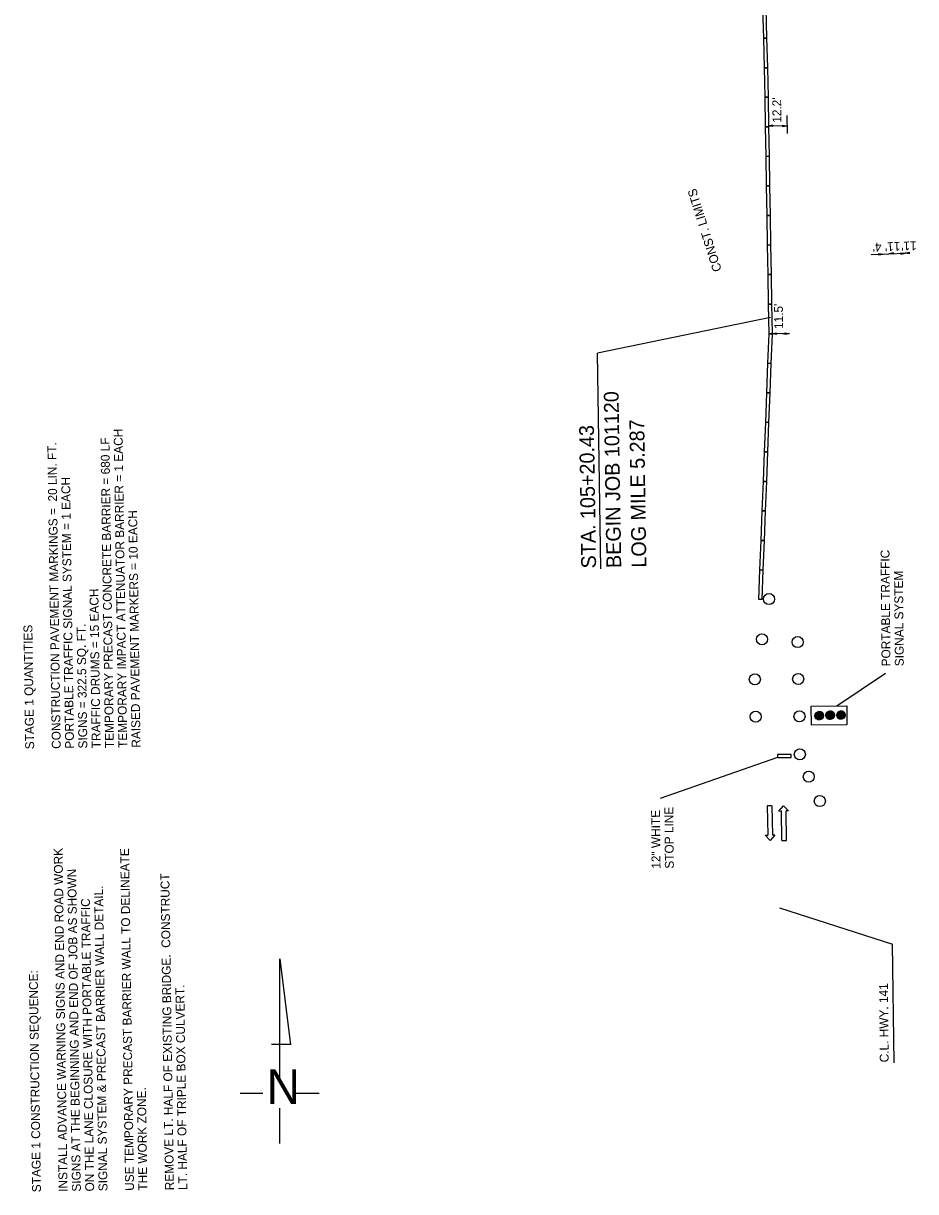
# Model space of a CAD drawing. Extents: x 1770018 to 1773492, y 718230 to 729141.
# Drawn here: x 1770318 to 1770922, y 724066 to 724857 of the extents above; entities that cross this region are included whole.
import ezdxf

# ---------------------------------------------------------------- set-up
doc = ezdxf.new("R2010")
doc.units = 0
for name, color, linetype in [('Default', 7, 'Continuous'), ('R_Border Notes', 7, 'Continuous'), ('R_Dimension', 7, 'Continuous'), ('R_Draft', 7, 'Continuous'), ('R_Horz Alg Annot', 7, 'Continuous'), ('R_MOT', 7, 'Continuous'), ('R_Proposed Road', 7, 'Continuous'), ('R_Striping', 7, 'Continuous'), ('T_Vehicle Path Rt', 7, 'Continuous')]:
    doc.layers.add(name, color=color, linetype=linetype)

msp = doc.modelspace()

# ---------------------------------------------------------------- linework, layer by layer
at = {"layer": 'Default'}
for p, q in [((1770823.66, 724657.68), (1770706.62, 724633.36)), ((1770708.87, 724487.41), (1770706.62, 724633.36)), ((1770856.85, 724385.28), (1770853.82, 724388.26)), ((1770856.67, 724385.28), (1770853.82, 724388.09)), ((1770857.01, 724385.3), (1770853.83, 724388.43)), ((1770856.49, 724385.29), (1770853.83, 724387.9)), ((1770857.17, 724385.32), (1770853.85, 724388.58)), ((1770856.29, 724385.31), (1770853.85, 724387.7)), ((1770857.32, 724385.35), (1770853.87, 724388.73)), ((1770856.07, 724385.35), (1770853.89, 724387.48)), ((1770857.46, 724385.38), (1770853.91, 724388.87)), ((1770857.6, 724385.43), (1770853.95, 724389.01)), ((1770855.83, 724385.41), (1770853.96, 724387.24)), ((1770857.73, 724385.47), (1770853.99, 724389.14)), ((1770857.85, 724385.52), (1770854.04, 724389.27)), ((1770855.54, 724385.52), (1770854.08, 724386.95)), ((1770857.97, 724385.58), (1770854.09, 724389.39)), ((1770858.09, 724385.64), (1770854.15, 724389.51)), ((1770858.2, 724385.71), (1770854.22, 724389.62)), ((1770858.31, 724385.78), (1770854.29, 724389.73)), ((1770855.15, 724385.73), (1770854.29, 724386.57)), ((1770858.41, 724385.85), (1770854.36, 724389.83)), ((1770858.51, 724385.93), (1770854.43, 724389.93)), ((1770858.61, 724386.01), (1770854.51, 724390.03)), ((1770858.7, 724386.1), (1770854.6, 724390.12)), ((1770858.78, 724386.18), (1770854.68, 724390.21)), ((1770858.87, 724386.28), (1770854.78, 724390.3)), ((1770858.95, 724386.37), (1770854.87, 724390.38)), ((1770859.02, 724386.48), (1770854.97, 724390.46)), ((1770859.1, 724386.58), (1770855.07, 724390.53)), ((1770859.16, 724386.69), (1770855.18, 724390.6)), ((1770859.23, 724386.8), (1770855.29, 724390.67)), ((1770859.29, 724386.92), (1770855.41, 724390.73)), ((1770859.34, 724387.04), (1770855.53, 724390.78)), ((1770859.39, 724387.17), (1770855.66, 724390.84)), ((1770859.43, 724387.3), (1770855.79, 724390.88)), ((1770859.47, 724387.44), (1770855.92, 724390.92)), ((1770859.51, 724387.58), (1770856.06, 724390.96)), ((1770859.53, 724387.73), (1770856.21, 724390.99)), ((1770859.55, 724387.88), (1770856.37, 724391.01)), ((1770859.56, 724388.05), (1770856.53, 724391.02)), ((1770859.56, 724388.22), (1770856.71, 724391.03)), ((1770859.55, 724388.41), (1770856.89, 724391.02)), ((1770859.53, 724388.61), (1770857.09, 724391)), ((1770859.49, 724388.83), (1770857.31, 724390.96)), ((1770859.42, 724389.07), (1770857.56, 724390.89)), ((1770859.3, 724389.36), (1770857.85, 724390.79)), ((1770859.08, 724389.74), (1770858.24, 724390.58)), ((1770864.33, 724385.61), (1770861.3, 724388.59)), ((1770864.16, 724385.61), (1770861.3, 724388.42)), ((1770864.49, 724385.63), (1770861.31, 724388.75)), ((1770863.97, 724385.62), (1770861.31, 724388.23)), ((1770864.65, 724385.65), (1770861.33, 724388.91)), ((1770863.77, 724385.64), (1770861.33, 724388.03)), ((1770864.8, 724385.68), (1770861.36, 724389.06)), ((1770863.55, 724385.68), (1770861.38, 724387.81)), ((1770864.94, 724385.71), (1770861.39, 724389.2)), ((1770865.08, 724385.75), (1770861.43, 724389.34)), ((1770863.31, 724385.74), (1770861.45, 724387.57)), ((1770865.21, 724385.8), (1770861.47, 724389.47)), ((1770865.33, 724385.85), (1770861.52, 724389.6)), ((1770863.02, 724385.85), (1770861.56, 724387.28)), ((1770865.45, 724385.91), (1770861.58, 724389.72)), ((1770865.57, 724385.97), (1770861.64, 724389.84)), ((1770865.68, 724386.04), (1770861.7, 724389.95)), ((1770865.79, 724386.11), (1770861.77, 724390.06)), ((1770862.63, 724386.06), (1770861.78, 724386.9)), ((1770865.89, 724386.18), (1770861.84, 724390.16)), ((1770865.99, 724386.26), (1770861.92, 724390.26)), ((1770866.09, 724386.34), (1770862, 724390.36)), ((1770866.18, 724386.42), (1770862.08, 724390.45)), ((1770866.27, 724386.51), (1770862.17, 724390.54)), ((1770866.35, 724386.61), (1770862.26, 724390.63)), ((1770866.43, 724386.7), (1770862.35, 724390.71)), ((1770866.51, 724386.8), (1770862.45, 724390.79)), ((1770866.58, 724386.91), (1770862.56, 724390.86)), ((1770866.65, 724387.02), (1770862.66, 724390.93)), ((1770866.71, 724387.13), (1770862.78, 724391)), ((1770866.77, 724387.25), (1770862.89, 724391.06)), ((1770866.82, 724387.37), (1770863.01, 724391.11)), ((1770866.87, 724387.5), (1770863.14, 724391.17)), ((1770866.92, 724387.63), (1770863.27, 724391.21)), ((1770866.96, 724387.76), (1770863.4, 724391.25)), ((1770866.99, 724387.91), (1770863.55, 724391.29)), ((1770867.02, 724388.06), (1770863.7, 724391.32)), ((1770867.03, 724388.21), (1770863.85, 724391.34)), ((1770867.05, 724388.38), (1770864.02, 724391.35)), ((1770867.05, 724388.55), (1770864.19, 724391.36)), ((1770867.04, 724388.74), (1770864.38, 724391.35)), ((1770867.01, 724388.94), (1770864.58, 724391.33)), ((1770866.97, 724389.15), (1770864.79, 724391.29)), ((1770866.9, 724389.4), (1770865.04, 724391.22)), ((1770866.78, 724389.69), (1770865.33, 724391.11)), ((1770866.57, 724390.07), (1770865.72, 724390.91)), ((1770871.67, 724385.68), (1770868.57, 724388.73)), ((1770871.5, 724385.67), (1770868.57, 724388.56)), ((1770871.32, 724385.67), (1770868.57, 724388.38)), ((1770871.83, 724385.7), (1770868.59, 724388.89)), ((1770871.13, 724385.69), (1770868.59, 724388.19)), ((1770871.99, 724385.72), (1770868.61, 724389.04)), ((1770870.92, 724385.72), (1770868.62, 724387.98)), ((1770872.13, 724385.76), (1770868.64, 724389.19)), ((1770872.27, 724385.79), (1770868.68, 724389.33)), ((1770870.69, 724385.77), (1770868.68, 724387.75)), ((1770872.41, 724385.84), (1770868.72, 724389.46)), ((1770872.53, 724385.89), (1770868.76, 724389.59)), ((1770870.42, 724385.86), (1770868.77, 724387.48)), ((1770872.66, 724385.94), (1770868.82, 724389.72)), ((1770872.78, 724386), (1770868.87, 724389.84)), ((1770872.89, 724386.06), (1770868.93, 724389.95)), ((1770870.09, 724386.01), (1770868.93, 724387.15)), ((1770873, 724386.13), (1770869, 724390.06)), ((1770873.11, 724386.2), (1770869.07, 724390.17)), ((1770873.21, 724386.28), (1770869.14, 724390.27)), ((1770873.31, 724386.36), (1770869.22, 724390.37)), ((1770873.4, 724386.44), (1770869.3, 724390.47)), ((1770873.49, 724386.53), (1770869.39, 724390.56)), ((1770873.57, 724386.62), (1770869.48, 724390.64)), ((1770873.66, 724386.71), (1770869.57, 724390.73)), ((1770873.73, 724386.81), (1770869.67, 724390.81)), ((1770873.81, 724386.91), (1770869.77, 724390.88)), ((1770873.88, 724387.02), (1770869.87, 724390.96)), ((1770873.94, 724387.13), (1770869.98, 724391.02)), ((1770874.01, 724387.25), (1770870.1, 724391.09)), ((1770874.06, 724387.37), (1770870.21, 724391.15)), ((1770874.16, 724387.62), (1770870.46, 724391.25)), ((1770874.2, 724387.75), (1770870.6, 724391.3)), ((1770874.24, 724387.89), (1770870.74, 724391.33)), ((1770874.27, 724388.04), (1770870.88, 724391.37)), ((1770874.29, 724388.19), (1770871.03, 724391.39)), ((1770874.31, 724388.35), (1770871.19, 724391.41)), ((1770874.32, 724388.52), (1770871.36, 724391.42)), ((1770874.31, 724388.7), (1770871.54, 724391.42)), ((1770874.3, 724388.89), (1770871.73, 724391.41)), ((1770874.26, 724389.09), (1770871.94, 724391.38)), ((1770874.21, 724389.32), (1770872.17, 724391.33)), ((1770874.12, 724389.58), (1770872.43, 724391.25)), ((1770873.98, 724389.9), (1770872.75, 724391.11)), ((1770873.59, 724390.46), (1770873.32, 724390.73)), ((1770829.81, 724258.16), (1770906.27, 724233.44)), ((1770907.5, 724153.27), (1770906.27, 724233.44))]:
    msp.add_line(p, q, dxfattribs=at)
msp.add_lwpolyline([(1770851.52, 724381.68), (1770851.4, 724394.67), (1770875.38, 724394.88), (1770875.49, 724381.89)], close=True, dxfattribs=at)
for centre in [(1770856.69, 724388.15), (1770864.17, 724388.48), (1770871.44, 724388.55)]:
    msp.add_circle(centre, 2.87, dxfattribs=at)
at = {"layer": 'R_Border Notes'}
for p, q in [((1770824.76, 724327.24), (1770821.56, 724327.19)), ((1770821.56, 724327.19), (1770821.87, 724307.21)), ((1770824.76, 724327.24), (1770825.07, 724307.25)), ((1770829.51, 724323.63), (1770832.65, 724327.19)), ((1770829.51, 724323.63), (1770831.11, 724323.66)), ((1770831.41, 724303.68), (1770831.11, 724323.66)), ((1770832.65, 724327.19), (1770835.91, 724323.73)), ((1770835.91, 724323.73), (1770834.31, 724323.71)), ((1770834.61, 724303.73), (1770834.31, 724323.71)), ((1770820.27, 724307.18), (1770821.87, 724307.21)), ((1770823.52, 724303.72), (1770820.27, 724307.18)), ((1770826.67, 724307.28), (1770823.52, 724303.72)), ((1770826.67, 724307.28), (1770825.07, 724307.25)), ((1770831.41, 724303.68), (1770834.61, 724303.73))]:
    msp.add_line(p, q, dxfattribs=at)
at = {"layer": 'R_Dimension'}
for p, q in [((1770868.64, 724394.82), (1770901.51, 724416.91)), ((1770828.45, 724359.77), (1770749.03, 724332.07))]:
    msp.add_line(p, q, dxfattribs=at)
at = {"layer": 'R_Draft'}
for p, q in [((1770491.63, 724223.55), (1770498.91, 724165.36)), ((1770491.63, 724142.19), (1770491.63, 724223.55)), ((1770485.98, 724165.79), (1770498.92, 724165.79)), ((1770464.87, 724132.6), (1770480.3, 724132.6)), ((1770501.9, 724132.6), (1770518.38, 724132.6)), ((1770491.63, 724098.55), (1770491.63, 724122.47))]:
    msp.add_line(p, q, dxfattribs=at)
at = {"layer": 'R_MOT'}
for centre in [(1770822.78, 724467.04), (1770817.98, 724439.86), (1770842.15, 724437.94), (1770813.19, 724412.69), (1770842.5, 724412.95), (1770813.7, 724387.44), (1770843.38, 724387.7), (1770843.63, 724361.98), (1770849.67, 724346.83), (1770857.14, 724330.34)]:
    msp.add_circle(centre, 3.75, dxfattribs=at)
at = {"layer": 'R_Proposed Road'}
for p, q in [((1770825.44, 724787.66), (1770822.45, 724787.16)), ((1770825.45, 724786.76), (1770822.45, 724787.16)), ((1770825.44, 724787.59), (1770822.95, 724787.17)), ((1770825.45, 724786.84), (1770822.95, 724787.17)), ((1770825.44, 724787.51), (1770823.46, 724787.18)), ((1770825.45, 724786.91), (1770823.46, 724787.18)), ((1770825.44, 724787.43), (1770823.96, 724787.18)), ((1770825.45, 724786.99), (1770823.96, 724787.18)), ((1770825.44, 724787.36), (1770824.47, 724787.19)), ((1770825.45, 724787.06), (1770824.47, 724787.19)), ((1770825.44, 724787.28), (1770824.97, 724787.2)), ((1770825.45, 724787.14), (1770824.97, 724787.2)), ((1770825.45, 724786.76), (1770825.44, 724787.66)), ((1770831.86, 724787.77), (1770834.87, 724787.37)), ((1770831.86, 724787.77), (1770831.88, 724786.87)), ((1770831.86, 724787.69), (1770834.37, 724787.36)), ((1770831.86, 724787.62), (1770833.85, 724787.35)), ((1770831.87, 724787.54), (1770833.35, 724787.34)), ((1770831.87, 724787.47), (1770832.84, 724787.34)), ((1770831.87, 724787.39), (1770832.34, 724787.33)), ((1770831.87, 724787.02), (1770833.85, 724787.35)), ((1770831.87, 724787.17), (1770832.84, 724787.34)), ((1770831.87, 724787.1), (1770833.35, 724787.34)), ((1770831.87, 724787.25), (1770832.34, 724787.33)), ((1770831.88, 724786.87), (1770834.87, 724787.37)), ((1770831.88, 724786.94), (1770834.37, 724787.36)), ((1770891.93, 724700.23), (1770899.93, 724700.53)), ((1770896.91, 724700.88), (1770899.93, 724700.54)), ((1770896.91, 724700.88), (1770896.94, 724699.98)), ((1770896.91, 724700.8), (1770899.42, 724700.52)), ((1770896.92, 724700.72), (1770898.91, 724700.5)), ((1770896.92, 724700.65), (1770898.41, 724700.48)), ((1770896.92, 724700.57), (1770897.9, 724700.46)), ((1770896.93, 724700.5), (1770897.4, 724700.44)), ((1770896.93, 724700.28), (1770897.9, 724700.46)), ((1770896.93, 724700.36), (1770897.4, 724700.44)), ((1770896.94, 724699.98), (1770899.93, 724700.54)), ((1770896.94, 724700.05), (1770899.42, 724700.52)), ((1770896.94, 724700.13), (1770898.91, 724700.5)), ((1770896.94, 724700.2), (1770898.41, 724700.48)), ((1770899.93, 724700.54), (1770903.92, 724700.69)), ((1770906.9, 724701.25), (1770903.92, 724700.69)), ((1770903.92, 724700.69), (1770914.92, 724701.1)), ((1770906.94, 724700.35), (1770903.92, 724700.69)), ((1770906.91, 724701.18), (1770904.42, 724700.71)), ((1770906.93, 724700.43), (1770904.42, 724700.71)), ((1770906.91, 724701.1), (1770904.94, 724700.73)), ((1770906.93, 724700.5), (1770904.94, 724700.73)), ((1770906.91, 724701.02), (1770905.44, 724700.75)), ((1770906.93, 724700.58), (1770905.44, 724700.75)), ((1770906.92, 724700.95), (1770905.95, 724700.76)), ((1770906.93, 724700.66), (1770905.95, 724700.76)), ((1770906.92, 724700.87), (1770906.45, 724700.78)), ((1770906.92, 724700.73), (1770906.45, 724700.78)), ((1770906.94, 724700.35), (1770906.9, 724701.25)), ((1770911.9, 724701.44), (1770914.92, 724701.1)), ((1770911.9, 724701.44), (1770911.93, 724700.54)), ((1770911.9, 724701.36), (1770914.41, 724701.08)), ((1770911.91, 724701.29), (1770913.9, 724701.06)), ((1770911.91, 724701.21), (1770913.4, 724701.04)), ((1770911.91, 724701.13), (1770912.89, 724701.02)), ((1770911.91, 724701.06), (1770912.39, 724701.01)), ((1770911.92, 724700.84), (1770912.89, 724701.02)), ((1770911.92, 724700.92), (1770912.39, 724701.01)), ((1770911.93, 724700.54), (1770914.92, 724701.1)), ((1770911.93, 724700.61), (1770914.41, 724701.08)), ((1770911.93, 724700.69), (1770913.9, 724701.06)), ((1770911.93, 724700.76), (1770913.4, 724701.04)), ((1770917.9, 724701.66), (1770914.92, 724701.1)), ((1770917.93, 724700.76), (1770914.92, 724701.1)), ((1770917.9, 724701.59), (1770915.42, 724701.12)), ((1770917.93, 724700.84), (1770915.42, 724701.12)), ((1770917.9, 724701.51), (1770915.93, 724701.14)), ((1770917.92, 724700.91), (1770915.93, 724701.14)), ((1770917.9, 724701.44), (1770916.43, 724701.16)), ((1770917.92, 724700.99), (1770916.43, 724701.16)), ((1770917.91, 724701.36), (1770916.94, 724701.18)), ((1770917.92, 724701.07), (1770916.94, 724701.18)), ((1770917.91, 724701.28), (1770917.44, 724701.19)), ((1770917.92, 724701.14), (1770917.44, 724701.19)), ((1770917.93, 724700.76), (1770917.9, 724701.66)), ((1770827.85, 724647.07), (1770824.85, 724646.57)), ((1770827.86, 724646.17), (1770824.85, 724646.57)), ((1770827.85, 724646.99), (1770825.36, 724646.58)), ((1770827.86, 724646.24), (1770825.36, 724646.58)), ((1770827.85, 724646.92), (1770825.87, 724646.58)), ((1770827.86, 724646.32), (1770825.87, 724646.58)), ((1770827.85, 724646.84), (1770826.37, 724646.59)), ((1770827.86, 724646.4), (1770826.37, 724646.59)), ((1770827.85, 724646.77), (1770826.88, 724646.6)), ((1770827.86, 724646.47), (1770826.88, 724646.6)), ((1770827.85, 724646.69), (1770827.38, 724646.61)), ((1770827.86, 724646.55), (1770827.38, 724646.61)), ((1770827.86, 724646.17), (1770827.85, 724647.07)), ((1770831.8, 724646.69), (1770835.8, 724646.75)), ((1770833.5, 724647.16), (1770836.51, 724646.77)), ((1770833.5, 724647.16), (1770833.52, 724646.26)), ((1770833.5, 724647.09), (1770836.01, 724646.76)), ((1770833.51, 724647.01), (1770835.49, 724646.75)), ((1770833.51, 724646.94), (1770834.99, 724646.74)), ((1770833.51, 724646.86), (1770834.49, 724646.73)), ((1770833.51, 724646.79), (1770833.99, 724646.72)), ((1770833.51, 724646.57), (1770834.49, 724646.73)), ((1770833.51, 724646.64), (1770833.99, 724646.72)), ((1770833.52, 724646.26), (1770836.51, 724646.77)), ((1770833.52, 724646.34), (1770836.01, 724646.76)), ((1770833.52, 724646.42), (1770835.49, 724646.75)), ((1770833.52, 724646.49), (1770834.99, 724646.74))]:
    msp.add_line(p, q, dxfattribs=at)
at = {"layer": 'R_Striping'}
for p, q in [((1770834.87, 724787.37), (1770822.45, 724787.16)), ((1770834.75, 724794.32), (1770834.96, 724782.16)), ((1770836.57, 724646.77), (1770824.85, 724646.57)), ((1770837.78, 724361.92), (1770828.42, 724361.77)), ((1770828.42, 724361.77), (1770828.45, 724359.77)), ((1770837.8, 724359.92), (1770837.78, 724361.92)), ((1770828.45, 724359.77), (1770837.8, 724359.92))]:
    msp.add_line(p, q, dxfattribs=at)
for points in [[(1770837.78, 724361.92), (1770837.78, 724361.92)], [(1770837.8, 724359.92), (1770837.8, 724359.92)]]:
    msp.add_lwpolyline(points, dxfattribs=at)
at = {"layer": 'T_Vehicle Path Rt'}
for points in [[(1770819.17, 724846.62), (1770818.56, 724866.61), (1770820.56, 724866.67), (1770821.17, 724846.68)], [(1770819.77, 724826.63), (1770819.17, 724846.62), (1770821.17, 724846.68), (1770821.77, 724826.69)], [(1770820.11, 724806.63), (1770819.77, 724826.63), (1770821.77, 724826.66), (1770822.11, 724806.66)], [(1770820.45, 724786.63), (1770820.11, 724806.63), (1770822.11, 724806.66), (1770822.45, 724786.67)], [(1770820.8, 724766.64), (1770820.45, 724786.63), (1770822.45, 724786.67), (1770822.8, 724766.67)], [(1770821.14, 724746.64), (1770820.8, 724766.64), (1770822.8, 724766.67), (1770823.14, 724746.67)], [(1770821.48, 724726.64), (1770821.14, 724746.64), (1770823.14, 724746.67), (1770823.48, 724726.68)], [(1770821.82, 724706.64), (1770821.48, 724726.64), (1770823.48, 724726.68), (1770823.82, 724706.68)], [(1770822.16, 724686.65), (1770821.82, 724706.64), (1770823.82, 724706.68), (1770824.16, 724686.68)], [(1770822.5, 724666.65), (1770822.16, 724686.65), (1770824.16, 724686.68), (1770824.5, 724666.68)], [(1770822.84, 724646.65), (1770822.5, 724666.65), (1770824.5, 724666.68), (1770824.84, 724646.69)], [(1770822.07, 724626.66), (1770822.86, 724646.65), (1770824.85, 724646.57), (1770824.07, 724626.58)], [(1770821.29, 724606.68), (1770822.07, 724626.66), (1770824.07, 724626.58), (1770823.29, 724606.6)], [(1770820.51, 724586.69), (1770821.29, 724606.68), (1770823.29, 724606.6), (1770822.51, 724586.61)], [(1770819.73, 724566.71), (1770820.51, 724586.69), (1770822.51, 724586.61), (1770821.73, 724566.63)], [(1770818.95, 724546.72), (1770819.73, 724566.71), (1770821.73, 724566.63), (1770820.95, 724546.64)], [(1770818.17, 724526.74), (1770818.95, 724546.72), (1770820.95, 724546.64), (1770820.16, 724526.66)], [(1770817.38, 724506.75), (1770818.17, 724526.74), (1770820.16, 724526.66), (1770819.38, 724506.67)], [(1770816.6, 724486.77), (1770817.38, 724506.75), (1770819.38, 724506.67), (1770818.6, 724486.69)], [(1770815.82, 724466.78), (1770816.6, 724486.77), (1770818.6, 724486.69), (1770817.82, 724466.71)]]:
    msp.add_lwpolyline(points, close=True, dxfattribs=at)

# ---------------------------------------------------------------- texts
at = {"layer": 'Default'}
for s, p in [('BEGIN JOB 101120', (1770722.77, 724488.12)), ('STA. 105+20.43', (1770705.74, 724487.86)), ('LOG MILE 5.287', (1770739.81, 724488.38))]:
    msp.add_text(s, height=10, rotation=90.88269, dxfattribs=at).set_placement(p)
at = {"layer": 'R_Dimension'}
for s, rotation, p in [("12.2'", 90.88269, (1770831.18, 724789.43)), ('CONST. LIMITS', 107.49703, (1770790.84, 724689.65)), ("11.5'", 90.88269, (1770832.35, 724649.81)), ('PORTABLE TRAFFIC', 90.50571, (1770904.97, 724421.54)), ('SIGNAL SYSTEM', 90.50571, (1770913.97, 724421.62)), ('12" WHITE', 90.50571, (1770749.34, 724284.56)), ('STOP LINE', 90.50571, (1770758.34, 724284.64))]:
    msp.add_text(s, height=6, rotation=rotation, dxfattribs=at).set_placement(p)
at = {"layer": 'R_Draft'}
for s, p in [('TEMPORARY IMPACT ATTENUATOR BARRIER = 1 EACH', (1770388.45, 724366.38)), ('TEMPORARY PRECAST CONCRETE BARRIER = 680 LF', (1770379.45, 724366.25)), ('CONSTRUCTION PAVEMENT MARKINGS =  20 LIN. FT.', (1770343.45, 724365.72)), ('PORTABLE TRAFFIC SIGNAL SYSTEM = 1 EACH', (1770352.45, 724365.85)), ('RAISED PAVEMENT MARKERS = 10 EACH', (1770397.44, 724366.51)), ('TRAFFIC DRUMS = 15 EACH', (1770370.45, 724366.11)), ('STAGE 1 QUANTITIES', (1770325.45, 724365.45)), ('SIGNS = 322.5 SQ. FT.', (1770361.45, 724365.98)), ('INSTALL ADVANCE WARNING SIGNS AND END ROAD WORK ', (1770348.07, 724065.98)), ('USE TEMPORARY PRECAST BARRIER WALL TO DELINEATE', (1770393.06, 724066.64)), ('SIGNS AT THE BEGINNING AND END OF JOB AS SHOWN ', (1770357.07, 724066.11)), ('REMOVE LT. HALF OF EXISTING BRIDGE.  CONSTRUCT', (1770420.06, 724067.04)), ('SIGNAL SYSTEM & PRECAST BARRIER WALL DETAIL.', (1770375.07, 724066.38)), ('ON THE LANE CLOSURE WITH PORTABLE TRAFFIC ', (1770366.07, 724066.24)), ('STAGE 1 CONSTRUCTION SEQUENCE:', (1770330.07, 724065.71)), ('LT. HALF OF TRIPLE BOX CULVERT. ', (1770429.06, 724067.18)), ('THE WORK ZONE. ', (1770402.06, 724066.78))]:
    msp.add_text(s, height=6, rotation=90.84663, dxfattribs=at).set_placement(p)
msp.add_text('N', height=23.27, dxfattribs=at).set_placement((1770482.8, 724125.44))
at = {"layer": 'R_Horz Alg Annot'}
msp.add_text('C.L. HWY. 141', height=6, rotation=90.50367, dxfattribs=at).set_placement((1770903.73, 724153.57))
at = {"layer": 'R_Proposed Road'}
for s, p in [("4'", (1770898.8, 724708.34)), ("11'", (1770911.58, 724708.83)), ("11'", (1770922.57, 724709.24))]:
    msp.add_text(s, height=6, rotation=182.14372, dxfattribs=at).set_placement(p)

doc.saveas('drawing.dxf')
